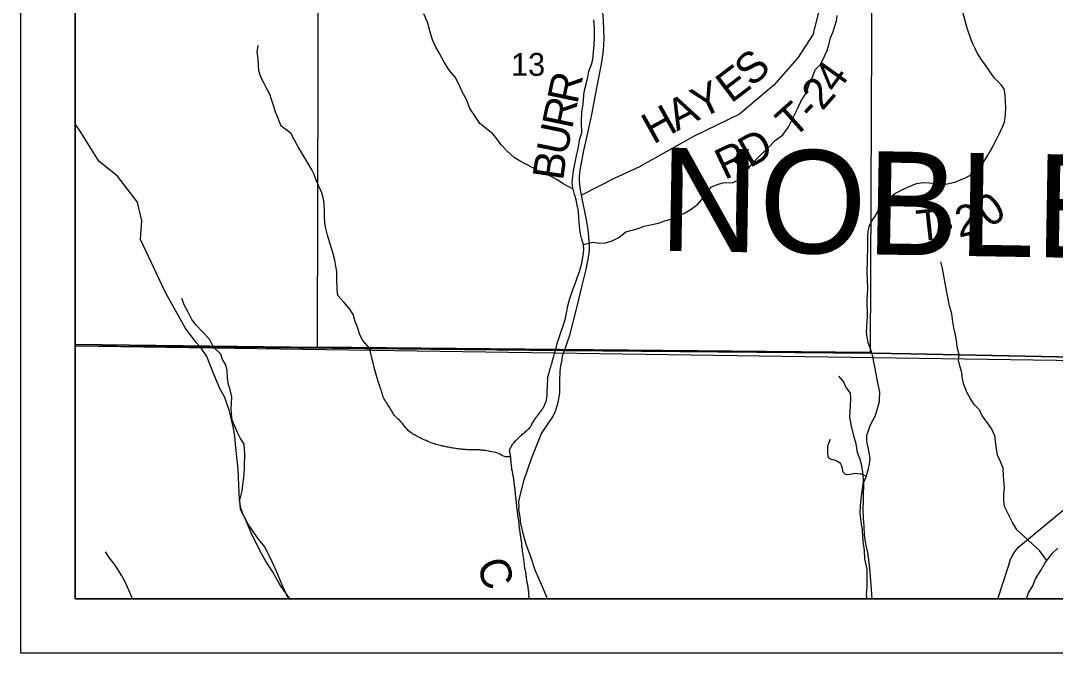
# Model space of a CAD drawing. Extents: x 0 to 34, y 0 to 22.
# Drawn here: x 23.417 to 25.315, y 14 to 15.161 of the extents above; entities that cross this region are included whole.
import ezdxf

# ---------------------------------------------------------------- set-up
doc = ezdxf.new("R2010")
doc.units = 0
for name, color, linetype in [('GM_X_Corporation', 7, 'Continuous'), ('GM_X_County', 7, 'Continuous'), ('GM_X_County_Road', 7, 'Continuous'), ('GM_X_County_Road_Text', 7, 'Continuous'), ('GM_X_County_Text', 7, 'Continuous'), ('GM_X_Minor_River', 7, 'Continuous'), ('GM_X_Section_Text', 7, 'Continuous'), ('GM_X_Township_Road', 7, 'Continuous'), ('GM_X_Township_Road_Text', 7, 'Continuous'), ('SH_Data', 7, 'Continuous')]:
    doc.layers.add(name, color=color, linetype=linetype)

msp = doc.modelspace()

# ---------------------------------------------------------------- linework, layer by layer
at = {"layer": 'GM_X_Corporation'}
msp.add_lwpolyline([(23.5167, 20.3276), (23.5167, 14.5642), (23.7464, 14.562), (24.4108, 14.5557), (24.414, 14.5556), (24.9788, 14.5503), (25.0494, 14.5496), (25.56, 14.5392), (26.009, 14.53), (26.3333, 14.5233), (26.7998, 14.5186), (27.0057, 14.5136), (27.0124, 14.988), (27.0234, 16.6611), (27.0349, 17.5522)], dxfattribs=at)
msp.add_lwpolyline([(23.5167, 20.3276), (23.5167, 14.5642), (23.7464, 14.562), (24.4108, 14.5557), (24.414, 14.5556), (24.9788, 14.5503), (25.0494, 14.5496), (25.56, 14.5392), (26.009, 14.53), (26.3333, 14.5233), (26.7998, 14.5186), (27.0057, 14.5136), (27.0124, 14.988), (27.0234, 16.6611), (27.0349, 17.5522)], dxfattribs=at)
for points in [[(23.5167, 15.5777), (23.5167, 14.5671), (23.9615, 14.5614), (23.9614, 14.5662), (23.9634, 15.5762)], [(23.9634, 15.5762), (24.9795, 15.5656), (24.9754, 14.552), (23.9615, 14.5614), (23.9614, 14.5662)], [(23.5167, 14.5642), (23.5167, 14.1), (30.3167, 14.1), (30.3167, 14.4639), (30.3098, 14.464), (29.2367, 14.4822), (29.1713, 14.4832), (28.7853, 14.4893), (28.4032, 14.497), (27.8031, 14.5091), (27.2999, 14.5107), (27.0057, 14.5136), (26.7998, 14.5186), (26.3333, 14.5233), (26.009, 14.53), (25.56, 14.5392), (25.0494, 14.5496), (24.9788, 14.5503), (24.414, 14.5556), (24.4108, 14.5557), (23.7464, 14.562)], [(23.5167, 14.5642), (23.5167, 14.1), (27.795, 14.1), (27.8031, 14.5091), (27.2999, 14.5107), (27.0057, 14.5136), (26.7998, 14.5186), (26.3333, 14.5233), (26.009, 14.53), (25.56, 14.5392), (25.0494, 14.5496), (24.9788, 14.5503), (24.414, 14.5556), (24.4108, 14.5557), (23.7464, 14.562)]]:
    msp.add_lwpolyline(points, close=True, dxfattribs=at)
at = {"layer": 'GM_X_County'}
msp.add_line((23.5167, 14.5642), (30.3167, 14.4639), dxfattribs=at)
at = {"layer": 'GM_X_County_Road'}
for points in [[(24.4142, 14.5551), (24.4199, 14.5712), (24.424, 14.5839), (24.4301, 14.6074), (24.4376, 14.636), (24.447, 14.6748), (24.4541, 14.7043), (24.4568, 14.717), (24.4589, 14.7295), (24.4601, 14.7401), (24.4602, 14.7477), (24.4598, 14.7568), (24.4577, 14.777), (24.4549, 14.7952), (24.4453, 14.8406), (24.4431, 14.8536), (24.4417, 14.8666), (24.4417, 14.8747), (24.4433, 14.8862), (24.45, 14.9222), (24.4555, 14.9461), (24.4607, 14.9713), (24.4644, 14.9883), (24.4745, 15.0405), (24.4822, 15.0808), (24.4854, 15.1009), (24.4866, 15.115), (24.4869, 15.1286), (24.4858, 15.1598), (24.4828, 15.2031)], [(24.3834, 14.1), (24.3719, 14.1263), (24.3605, 14.1526), (24.3523, 14.1767), (24.3441, 14.1993), (24.3391, 14.2174), (24.3348, 14.2355), (24.3339, 14.2415), (24.3334, 14.2457), (24.3329, 14.2491), (24.3324, 14.254), (24.3307, 14.2631), (24.3313, 14.2684), (24.3306, 14.2783), (24.3337, 14.292), (24.3402, 14.318), (24.3536, 14.3571), (24.3721, 14.4032), (24.3932, 14.4337), (24.3976, 14.4443), (24.4009, 14.4539), (24.4031, 14.4631), (24.4057, 14.4783), (24.4057, 14.4989), (24.4066, 14.5175), (24.4077, 14.5272), (24.4099, 14.5381), (24.4109, 14.5458), (24.4142, 14.5551)], [(25.2092, 14.1), (25.2296, 14.1618), (25.2313, 14.1687), (25.2327, 14.1725), (25.2342, 14.1752), (25.2363, 14.1795), (25.2381, 14.1826), (25.2403, 14.1864), (25.2443, 14.1911), (25.2476, 14.1954), (25.4286, 14.3447), (25.4438, 14.3563), (25.4541, 14.3664), (25.4637, 14.3782), (25.4725, 14.3877), (25.4808, 14.4011), (25.4947, 14.4212), (25.5133, 14.4528), (25.5302, 14.4822), (25.544, 14.509), (25.5602, 14.5386)]]:
    msp.add_lwpolyline(points, dxfattribs=at)
at = {"layer": 'GM_X_Minor_River'}
for points in [[(24.2589, 14.972), (24.2498, 14.9862), (24.2407, 14.9995), (24.2346, 15.0162), (24.2269, 15.0302), (24.2212, 15.0431), (24.2136, 15.0571), (24.2026, 15.07), (24.1934, 15.0844), (24.1847, 15.1018), (24.1782, 15.112), (24.1721, 15.1253), (24.1683, 15.1378), (24.1652, 15.1484), (24.1629, 15.1579), (24.1564, 15.1731)], [(24.8319, 14.9795), (24.8417, 14.9988), (24.8481, 15.0121), (24.8546, 15.0231), (24.8595, 15.0326), (24.864, 15.0452), (24.8697, 15.0588), (24.8742, 15.0706), (24.884, 15.0801), (24.8912, 15.0953), (24.8961, 15.106), (24.8991, 15.1162), (24.9021, 15.1292), (24.9067, 15.1387), (24.9097, 15.1485), (24.9131, 15.1603), (24.9146, 15.1698)], [(24.4453, 14.9744), (24.4463, 14.9933), (24.4486, 15.0066), (24.4493, 15.0161), (24.4504, 15.0298), (24.4542, 15.0438), (24.4572, 15.0571), (24.4591, 15.0678), (24.4636, 15.0799), (24.4662, 15.0894), (24.4677, 15.1027), (24.4685, 15.116), (24.4696, 15.1289), (24.4692, 15.1388), (24.4692, 15.1483), (24.468, 15.1623)], [(23.8943, 14.9672), (23.8886, 14.9828), (23.8844, 14.993), (23.8809, 15.0033), (23.8771, 15.0161), (23.8737, 15.0256), (23.8676, 15.037), (23.863, 15.0465), (23.8577, 15.0559), (23.8535, 15.0688), (23.8527, 15.0787), (23.8523, 15.0908), (23.8504, 15.1026), (23.8522, 15.1148)], [(24.449, 14.7501), (24.4666, 14.754), (24.4791, 14.7522), (24.4893, 14.753), (24.5021, 14.7565), (24.5142, 14.763), (24.5267, 14.773), (24.5384, 14.7765), (24.5493, 14.7796), (24.5603, 14.7834), (24.572, 14.7861), (24.5867, 14.7893), (24.5969, 14.7927), (24.6068, 14.7958), (24.6196, 14.8012), (24.6343, 14.8074), (24.6468, 14.815), (24.6592, 14.8238), (24.6667, 14.8334), (24.6739, 14.8429), (24.684, 14.8555), (24.6968, 14.8609), (24.7074, 14.8639), (24.7222, 14.8633), (24.732, 14.8671), (24.7422, 14.8786), (24.7516, 14.8892), (24.7628, 14.903), (24.776, 14.9159), (24.7888, 14.9282), (24.8008, 14.9407), (24.8148, 14.9514), (24.8249, 14.9644), (24.8319, 14.9795)], [(24.0571, 14.5589), (24.0445, 14.5736), (24.0391, 14.5842), (24.0352, 14.5967), (24.0306, 14.6085), (24.0264, 14.6213), (24.0203, 14.6311), (24.0104, 14.6436), (23.9986, 14.6561), (23.997, 14.6674), (23.9969, 14.689), (23.9964, 14.7004), (23.9948, 14.7099), (23.9929, 14.7213), (23.9898, 14.733), (23.9871, 14.7432), (23.984, 14.7531), (23.9798, 14.7671), (23.9767, 14.7796), (23.9747, 14.7894), (23.9743, 14.8016), (23.9742, 14.8111), (23.9734, 14.8243), (23.9722, 14.8338), (23.9691, 14.8448), (23.9629, 14.858), (23.9587, 14.8679), (23.9553, 14.8781), (23.9499, 14.8883), (23.9423, 14.9019), (23.9331, 14.9166), (23.9258, 14.9291), (23.9193, 14.9412), (23.9124, 14.9541), (23.8943, 14.9672)], [(24.4302, 14.8512), (24.4118, 14.8614), (24.4023, 14.8678), (24.3902, 14.875), (24.3803, 14.8787), (24.3674, 14.8836), (24.3564, 14.8907), (24.3424, 14.8982), (24.3329, 14.9031), (24.3218, 14.9098), (24.3089, 14.9212), (24.2979, 14.9328), (24.2906, 14.9434), (24.2826, 14.9532), (24.2589, 14.972)], [(24.3977, 14.5556), (24.4007, 14.5682), (24.4048, 14.5792), (24.4088, 14.5921), (24.4133, 14.6043), (24.4159, 14.6149), (24.4185, 14.6274), (24.4203, 14.6377), (24.424, 14.651), (24.4289, 14.6658), (24.4345, 14.6799), (24.4382, 14.6905), (24.4419, 14.7004), (24.446, 14.716), (24.4489, 14.7297), (24.4496, 14.7399), (24.4492, 14.7494), (24.4461, 14.7596), (24.4438, 14.7698), (24.4418, 14.7831), (24.4406, 14.7979), (24.4401, 14.8115), (24.4378, 14.8221), (24.4355, 14.832), (24.4324, 14.8418), (24.4297, 14.8536), (24.4285, 14.8638), (24.4295, 14.8756), (24.431, 14.8851), (24.4332, 14.8976), (24.4358, 14.9101), (24.4387, 14.9227), (24.4406, 14.9322), (24.4416, 14.9417), (24.4461, 14.955), (24.4453, 14.9744)], [(25.1385, 14.5475), (25.135, 14.563), (25.1338, 14.574), (25.131, 14.5873), (25.1287, 14.5971), (25.1271, 14.6081), (25.1252, 14.6229), (25.1209, 14.6373), (25.119, 14.6475), (25.1163, 14.6592), (25.1147, 14.6695), (25.1127, 14.6793), (25.11, 14.6922), (25.1077, 14.7062), (25.1049, 14.7184)], [(23.7701, 14.5616), (23.7628, 14.5765), (23.7507, 14.5889), (23.7381, 14.6025), (23.7308, 14.6123), (23.7239, 14.626), (23.7174, 14.6381), (23.7121, 14.6509)], [(23.9077, 14.1), (23.8975, 14.1226), (23.8865, 14.1491), (23.8756, 14.1733), (23.8639, 14.1959), (23.8512, 14.212), (23.8342, 14.2369), (23.8198, 14.2637), (23.8188, 14.2811), (23.8227, 14.2979), (23.8247, 14.3131), (23.8264, 14.3272), (23.8274, 14.3409), (23.8281, 14.366), (23.8267, 14.3838), (23.8201, 14.394), (23.8147, 14.4053), (23.8049, 14.4276), (23.8032, 14.4394), (23.8027, 14.4492), (23.8037, 14.4595), (23.8039, 14.4698), (23.8015, 14.4808), (23.7975, 14.4955), (23.7962, 14.5054), (23.7956, 14.5187), (23.7928, 14.5289), (23.787, 14.5391), (23.7838, 14.5489), (23.7701, 14.5616)], [(25.2994, 14.1705), (25.2859, 14.1884), (25.2729, 14.2004), (25.2564, 14.2158), (25.2449, 14.2262), (25.2363, 14.2402), (25.2285, 14.256), (25.2215, 14.2692), (25.2202, 14.2806), (25.2205, 14.292), (25.2214, 14.3038), (25.22, 14.3258), (25.2194, 14.3395), (25.2139, 14.3531), (25.2088, 14.3633), (25.2071, 14.375), (25.2041, 14.3989), (25.1979, 14.4125), (25.1905, 14.4227), (25.1805, 14.4358), (25.1758, 14.4464), (25.1658, 14.4562), (25.1588, 14.4678), (25.1523, 14.4788), (25.1471, 14.4931), (25.1447, 14.5034), (25.1434, 14.5147), (25.1394, 14.5272), (25.137, 14.5378), (25.1385, 14.5475)], [(24.9787, 14.1), (24.9774, 14.1169), (24.9754, 14.1488), (24.9733, 14.1666), (24.9711, 14.1848), (24.9674, 14.2011), (24.965, 14.2166), (24.964, 14.2329), (24.963, 14.2481), (24.9624, 14.2637), (24.9629, 14.2797), (24.9631, 14.2922), (24.9633, 14.3067), (24.9631, 14.3192), (24.9618, 14.3317), (24.9597, 14.3438), (24.9565, 14.3556), (24.9521, 14.3681), (24.9493, 14.384), (24.9449, 14.3991), (24.9408, 14.4165), (24.9379, 14.4332), (24.9386, 14.4431), (24.9392, 14.4537), (24.9397, 14.4674), (24.9388, 14.4773), (24.9307, 14.4886), (24.926, 14.4984), (24.9179, 14.5085)], [(23.6212, 14.1), (23.6204, 14.1032), (23.6153, 14.116), (23.6086, 14.1311), (23.602, 14.142), (23.5954, 14.1533), (23.5881, 14.1639), (23.5788, 14.1759), (23.5722, 14.1861)], [(25.2622, 14.1), (25.2659, 14.111), (25.2736, 14.124), (25.2787, 14.1367), (25.2872, 14.1501), (25.2961, 14.1662), (25.3091, 14.1831), (25.3192, 14.1931)]]:
    msp.add_lwpolyline(points, dxfattribs=at)
msp.add_spline([(24.3155, 14.3609), (24.3063, 14.3604), (24.2918, 14.3671), (24.2774, 14.3704), (24.2671, 14.3722), (24.2588, 14.373), (24.2497, 14.3733), (24.2394, 14.3732), (24.2307, 14.3739), (24.2223, 14.3746), (24.2117, 14.3761), (24.2014, 14.3779), (24.1931, 14.3797), (24.1839, 14.3819), (24.1733, 14.3849), (24.1604, 14.3901), (24.1516, 14.3939), (24.1425, 14.3988), (24.1341, 14.4036), (24.1234, 14.4138), (24.1115, 14.4274), (24.102, 14.4368), (24.097, 14.4452), (24.0916, 14.4539), (24.0862, 14.4622), (24.0808, 14.4728), (24.0785, 14.4811), (24.0754, 14.4902), (24.0571, 14.5589)], degree=3, dxfattribs=at)
msp.add_open_spline([(24.35, 14.1), (24.3498, 14.1011), (24.3496, 14.1021), (24.3494, 14.1032), (24.3488, 14.1079), (24.3489, 14.1126), (24.3482, 14.1172), (24.3477, 14.1204), (24.3472, 14.1236), (24.3466, 14.1267), (24.3461, 14.1296), (24.3455, 14.1325), (24.345, 14.1355), (24.3443, 14.1396), (24.3441, 14.1438), (24.3434, 14.148), (24.3429, 14.1512), (24.3419, 14.1543), (24.3415, 14.1575), (24.3409, 14.1619), (24.3405, 14.1663), (24.3399, 14.1707), (24.3391, 14.1763), (24.3382, 14.1819), (24.3375, 14.1874), (24.337, 14.1905), (24.3367, 14.1935), (24.3363, 14.1965), (24.3359, 14.1997), (24.3359, 14.2029), (24.3354, 14.206), (24.3349, 14.2102), (24.3341, 14.2143), (24.3335, 14.2185), (24.333, 14.2214), (24.3326, 14.2243), (24.3323, 14.2273), (24.3318, 14.2307), (24.3315, 14.2341), (24.3311, 14.2375), (24.3307, 14.2408), (24.3303, 14.2441), (24.3298, 14.2474), (24.3294, 14.251), (24.3287, 14.2547), (24.3282, 14.2584), (24.3276, 14.263), (24.3271, 14.2677), (24.3266, 14.2724), (24.3263, 14.2756), (24.3261, 14.2787), (24.3258, 14.2819), (24.3255, 14.2849), (24.3249, 14.288), (24.3246, 14.291), (24.3243, 14.2939), (24.3242, 14.2968), (24.3238, 14.2997), (24.3234, 14.3028), (24.323, 14.3058), (24.3226, 14.3088), (24.3222, 14.312), (24.3218, 14.3151), (24.3214, 14.3183), (24.3209, 14.3217), (24.3204, 14.3251), (24.3198, 14.3285), (24.3192, 14.332), (24.3182, 14.3353), (24.3178, 14.3388), (24.3174, 14.3427), (24.317, 14.3466), (24.3166, 14.3506), (24.3162, 14.3542), (24.3158, 14.3579), (24.3154, 14.3616), (24.3151, 14.3645), (24.3141, 14.3674), (24.3138, 14.3703), (24.3135, 14.3734), (24.315, 14.3765), (24.3168, 14.3794), (24.3188, 14.3829), (24.321, 14.3858), (24.3235, 14.3886), (24.3269, 14.3921), (24.3302, 14.3956), (24.3337, 14.3989), (24.3369, 14.4018), (24.3403, 14.4044), (24.3435, 14.4073), (24.3465, 14.4099), (24.3495, 14.4125), (24.3518, 14.4157), (24.354, 14.4187), (24.3554, 14.4221), (24.3574, 14.4252), (24.3595, 14.4284), (24.3616, 14.4317), (24.3638, 14.4348), (24.366, 14.4378), (24.3684, 14.4406), (24.3706, 14.4436), (24.3727, 14.4464), (24.3745, 14.4493), (24.3762, 14.4523), (24.3778, 14.4551), (24.379, 14.458), (24.38, 14.4611), (24.3811, 14.4645), (24.3819, 14.4678), (24.3822, 14.4713), (24.3824, 14.4744), (24.3823, 14.4774), (24.3825, 14.4805), (24.3827, 14.4835), (24.383, 14.4865), (24.3832, 14.4896), (24.3834, 14.4926), (24.3834, 14.4957), (24.3835, 14.4987), (24.3836, 14.5019), (24.3833, 14.5051), (24.3842, 14.5082), (24.3887, 14.524), (24.3932, 14.5398), (24.3977, 14.5556)], degree=3, dxfattribs=at)
at = {"layer": 'GM_X_Township_Road'}
for points in [[(25.0333, 15.7513), (25.0273, 15.7493), (25.0116, 15.7441), (24.9834, 15.7221), (24.9583, 15.6845), (24.9364, 15.6281), (24.9082, 15.5059), (24.905, 15.4307), (24.8925, 15.3116), (24.8862, 15.2019), (24.8736, 15.1489)], [(24.979, 14.5497), (24.9717, 14.57), (24.9698, 14.5798), (24.9683, 14.589), (24.9704, 14.6182), (24.9698, 14.6473), (24.9706, 14.6697), (24.9698, 14.6988), (24.971, 14.7442), (24.9708, 14.7563), (24.9709, 14.7656), (24.9715, 14.7729), (24.9722, 14.7774), (24.9735, 14.7825), (24.976, 14.7885), (24.9791, 14.7942), (24.9843, 14.8022), (24.9905, 14.8124), (24.9959, 14.8197), (25.0018, 14.8269), (25.0092, 14.8341), (25.0198, 14.843), (25.0323, 14.8495), (25.044, 14.8551), (25.0529, 14.859), (25.0603, 14.8617), (25.0723, 14.8635), (25.0831, 14.8632), (25.0985, 14.861), (25.1037, 14.8603), (25.1093, 14.8601), (25.1142, 14.8608), (25.1197, 14.8617), (25.1274, 14.8635), (25.134, 14.8658), (25.1419, 14.8689), (25.1501, 14.8721), (25.1577, 14.8765), (25.1634, 14.8813), (25.1689, 14.8866), (25.1824, 14.8996), (25.1959, 14.9215), (25.2062, 14.9415), (25.2114, 14.951), (25.2189, 14.968), (25.2214, 14.9749), (25.2229, 14.9822), (25.2237, 14.9894), (25.2241, 15.0006), (25.2237, 15.0132), (25.2229, 15.0224), (25.2214, 15.0331), (25.2203, 15.0361), (25.2182, 15.0394), (25.2155, 15.0428), (25.203, 15.0551), (25.1944, 15.0674), (25.1871, 15.0783), (25.1814, 15.0864), (25.1755, 15.0949), (25.1714, 15.1016), (25.1677, 15.1095), (25.164, 15.1169), (25.1604, 15.1255), (25.1532, 15.147), (25.1433, 15.1827)], [(24.8736, 15.1489), (24.872, 15.1425), (24.8705, 15.1361), (24.8423, 15.0923), (24.7984, 15.0421), (24.7357, 14.9889), (24.6511, 14.9481), (24.5508, 14.8917), (24.5133, 14.8747)], [(23.7466, 14.5614), (23.7388, 14.5704), (23.7184, 14.5968), (23.6822, 14.6622), (23.6362, 14.759), (23.6389, 14.7935), (23.631, 14.8276), (23.5942, 14.8751), (23.5598, 14.9029), (23.5267, 14.9562), (23.5167, 14.9716)], [(24.5133, 14.8747), (24.5064, 14.8715), (24.4453, 14.8406)], [(23.9102, 14.1), (23.9061, 14.1058), (23.8925, 14.1253), (23.8784, 14.1498), (23.8651, 14.1708), (23.8545, 14.19), (23.8387, 14.2224), (23.8307, 14.2417), (23.824, 14.256), (23.8204, 14.2665), (23.8179, 14.2813), (23.817, 14.3087), (23.8157, 14.3379), (23.8134, 14.3607), (23.8112, 14.3774), (23.8097, 14.3975), (23.8072, 14.413), (23.803, 14.4315), (23.7993, 14.4463), (23.7909, 14.4693), (23.7823, 14.4859), (23.7752, 14.5017), (23.766, 14.5244), (23.7581, 14.5444), (23.7466, 14.5614)], [(24.9922, 14.4655), (24.9931, 14.4791), (24.9895, 14.496), (24.9843, 14.5225), (24.979, 14.5497)], [(24.9699, 14.1), (24.9685, 14.1063), (24.9697, 14.123), (24.9694, 14.1405), (24.9695, 14.1545), (24.9654, 14.1731), (24.9647, 14.1887), (24.9625, 14.2053), (24.961, 14.2255), (24.9588, 14.2421), (24.9571, 14.2573), (24.9576, 14.2702), (24.9585, 14.2832), (24.9612, 14.3015), (24.9625, 14.3117), (24.9684, 14.3248), (24.9705, 14.3328), (24.9719, 14.3385), (24.9741, 14.3473), (24.9754, 14.3568), (24.9746, 14.3614), (24.9712, 14.3773), (24.9691, 14.3886), (24.9689, 14.3996), (24.9754, 14.4181), (24.985, 14.4364), (24.992, 14.4622), (24.9922, 14.4655)], [(24.9684, 14.3248), (24.9642, 14.3262), (24.9619, 14.3285), (24.9569, 14.3287), (24.9512, 14.329), (24.9466, 14.3297), (24.9421, 14.3289), (24.9338, 14.3272), (24.9296, 14.3283), (24.9257, 14.332), (24.9241, 14.3392), (24.9232, 14.3433), (24.9205, 14.3482), (24.9166, 14.3512), (24.9105, 14.3541), (24.9059, 14.3552), (24.9025, 14.3563), (24.8986, 14.3585), (24.8978, 14.3607), (24.8973, 14.3683), (24.8972, 14.374), (24.8975, 14.3801), (24.9004, 14.3885), (24.9026, 14.3931)]]:
    msp.add_lwpolyline(points, dxfattribs=at)
at = {"layer": 'SH_Data'}
for points in [[(23.4167, 21), (30.4167, 21), (30.4167, 14), (23.4167, 14)], [(23.5167, 20.9), (30.3167, 20.9), (30.3167, 14.1), (23.5167, 14.1)]]:
    msp.add_lwpolyline(points, close=True, dxfattribs=at)

# ---------------------------------------------------------------- texts
at = {"layer": 'GM_X_County_Road_Text'}
for s, rotation, p in [('R', 78.2514, (24.4378, 15.006)), ('R', 78.2522, (24.4283, 14.9603)), ('U', 78.4064, (24.4183, 14.9113)), ('B', 81.6138, (24.4116, 14.866)), ('C', 289.2508, (24.2524, 14.1638))]:
    msp.add_text(s, height=0.0568, rotation=rotation, dxfattribs=at).set_placement(p)
at = {"layer": 'GM_X_County_Text'}
msp.add_text('NOBLE COUNTY', height=0.189394, rotation=359.0214, dxfattribs=at).set_placement((24.5871, 14.7385))
at = {"layer": 'GM_X_Section_Text'}
msp.add_text('13', height=0.04186, rotation=0, dxfattribs=at).set_placement((24.3165, 15.0594))
at = {"layer": 'GM_X_Township_Road_Text'}
for s, rotation, p in [('S', 42.4638, (24.7584, 15.0373)), ('E', 37.0576, (24.72, 15.0079)), ('4', 54.3203, (24.9139, 15.0247)), ('2', 48.8308, (24.8872, 14.9937)), ('Y', 25.8303, (24.6646, 14.9798)), ('A', 27.1939, (24.6205, 14.9571)), ('T', 41.7193, (24.8341, 14.9429)), ('H', 29.0861, (24.5772, 14.933)), ('-', 46.855, (24.8698, 14.975)), ('D', 29.2454, (24.754, 14.8895)), ('R', 25.3361, (24.7081, 14.8677)), ('0', 34.2737, (25.1938, 14.7793)), ('2', 12.1348, (25.1377, 14.7626)), ('T', 6.2564, (25.063, 14.7556)), ('-', 2.7096, (25.1043, 14.7602))]:
    msp.add_text(s, height=0.0568, rotation=rotation, dxfattribs=at).set_placement(p)

doc.saveas('drawing.dxf')
